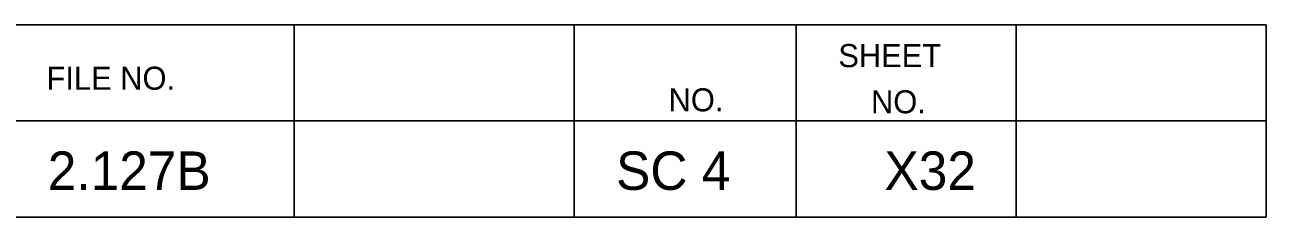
# Model space of a CAD drawing. Extents: x 1000 to 1162, y 999 to 8520.
# Drawn here: x 1145.41 to 1161.56, y 4665.05 to 4667.55 of the extents above; entities that cross this region are included whole.
import ezdxf

# ---------------------------------------------------------------- set-up
doc = ezdxf.new("R2010")
doc.units = 0
doc.layers.add('Level 20', color=7, linetype='Continuous')
doc.layers.add('Level 3', color=7, linetype='Continuous')

msp = doc.modelspace()

# ---------------------------------------------------------------- linework, layer by layer
at = {"layer": 'Level 3'}
for p, q in [((1133.055, 4667.546), (1161.555, 4667.546)), ((1133.055, 4667.546), (1161.555, 4667.546)), ((1133.055, 4667.546), (1161.555, 4667.546)), ((1133.055, 4667.546), (1161.555, 4667.546)), ((1133.055, 4667.546), (1161.555, 4667.546)), ((1133.055, 4667.546), (1161.555, 4667.546)), ((1133.055, 4667.546), (1161.555, 4667.546)), ((1133.055, 4667.546), (1161.555, 4667.546)), ((1133.055, 4667.546), (1161.555, 4667.546)), ((1133.055, 4667.546), (1161.555, 4667.546)), ((1133.055, 4667.546), (1161.555, 4667.546)), ((1133.055, 4667.546), (1161.555, 4667.546)), ((1133.055, 4667.546), (1161.555, 4667.546)), ((1133.055, 4667.546), (1161.555, 4667.546)), ((1133.055, 4667.546), (1161.555, 4667.546)), ((1133.055, 4667.546), (1161.555, 4667.546)), ((1133.055, 4667.546), (1161.555, 4667.546)), ((1133.055, 4667.546), (1161.555, 4667.546)), ((1133.055, 4667.546), (1161.555, 4667.546)), ((1133.055, 4667.546), (1161.555, 4667.546)), ((1133.055, 4667.546), (1161.555, 4667.546)), ((1133.055, 4667.546), (1161.555, 4667.546)), ((1133.055, 4667.546), (1161.555, 4667.546)), ((1133.055, 4667.546), (1161.555, 4667.546)), ((1133.055, 4667.546), (1161.555, 4667.546)), ((1133.055, 4667.546), (1161.555, 4667.546)), ((1133.055, 4667.546), (1161.555, 4667.546)), ((1133.055, 4667.546), (1161.555, 4667.546)), ((1133.055, 4667.546), (1161.555, 4667.546)), ((1133.055, 4667.546), (1161.555, 4667.546)), ((1148.913, 4667.546), (1148.913, 4665.046)), ((1148.913, 4667.546), (1148.913, 4665.046)), ((1148.913, 4667.546), (1148.913, 4665.046)), ((1148.913, 4667.546), (1148.913, 4665.046)), ((1148.913, 4667.546), (1148.913, 4665.046)), ((1148.913, 4667.546), (1148.913, 4665.046)), ((1148.913, 4667.546), (1148.913, 4665.046)), ((1148.913, 4667.546), (1148.913, 4665.046)), ((1148.913, 4667.546), (1148.913, 4665.046)), ((1148.913, 4667.546), (1148.913, 4665.046)), ((1148.913, 4667.546), (1148.913, 4665.046)), ((1148.913, 4667.546), (1148.913, 4665.046)), ((1148.913, 4667.546), (1148.913, 4665.046)), ((1148.913, 4667.546), (1148.913, 4665.046)), ((1148.913, 4667.546), (1148.913, 4665.046)), ((1148.913, 4667.546), (1148.913, 4665.046)), ((1148.913, 4667.546), (1148.913, 4665.046)), ((1148.913, 4667.546), (1148.913, 4665.046)), ((1148.913, 4667.546), (1148.913, 4665.046)), ((1148.913, 4667.546), (1148.913, 4665.046)), ((1148.913, 4667.546), (1148.913, 4665.046)), ((1148.913, 4667.546), (1148.913, 4665.046)), ((1148.913, 4667.546), (1148.913, 4665.046)), ((1148.913, 4667.546), (1148.913, 4665.046)), ((1148.913, 4667.546), (1148.913, 4665.046)), ((1148.913, 4667.546), (1148.913, 4665.046)), ((1148.913, 4667.546), (1148.913, 4665.046)), ((1148.913, 4667.546), (1148.913, 4665.046)), ((1148.913, 4667.546), (1148.913, 4665.046)), ((1148.913, 4667.546), (1148.913, 4665.046)), ((1152.554, 4667.546), (1152.554, 4665.046)), ((1152.554, 4667.546), (1152.554, 4665.046)), ((1152.554, 4667.546), (1152.554, 4665.046)), ((1152.554, 4667.546), (1152.554, 4665.046)), ((1152.554, 4667.546), (1152.554, 4665.046)), ((1152.554, 4667.546), (1152.554, 4665.046)), ((1152.554, 4667.546), (1152.554, 4665.046)), ((1152.554, 4667.546), (1152.554, 4665.046)), ((1152.554, 4667.546), (1152.554, 4665.046)), ((1152.554, 4667.546), (1152.554, 4665.046)), ((1152.554, 4667.546), (1152.554, 4665.046)), ((1152.554, 4667.546), (1152.554, 4665.046)), ((1152.554, 4667.546), (1152.554, 4665.046)), ((1152.554, 4667.546), (1152.554, 4665.046)), ((1152.554, 4667.546), (1152.554, 4665.046)), ((1152.554, 4667.546), (1152.554, 4665.046)), ((1152.554, 4667.546), (1152.554, 4665.046)), ((1152.554, 4667.546), (1152.554, 4665.046)), ((1152.554, 4667.546), (1152.554, 4665.046)), ((1152.554, 4667.546), (1152.554, 4665.046)), ((1152.554, 4667.546), (1152.554, 4665.046)), ((1152.554, 4667.546), (1152.554, 4665.046)), ((1152.554, 4667.546), (1152.554, 4665.046)), ((1152.554, 4667.546), (1152.554, 4665.046)), ((1152.554, 4667.546), (1152.554, 4665.046)), ((1152.554, 4667.546), (1152.554, 4665.046)), ((1152.554, 4667.546), (1152.554, 4665.046)), ((1152.554, 4667.546), (1152.554, 4665.046)), ((1152.554, 4667.546), (1152.554, 4665.046)), ((1152.554, 4667.546), (1152.554, 4665.046)), ((1155.44, 4667.546), (1155.44, 4665.046)), ((1155.44, 4667.546), (1155.44, 4665.046)), ((1155.44, 4667.546), (1155.44, 4665.046)), ((1155.44, 4667.546), (1155.44, 4665.046)), ((1155.44, 4667.546), (1155.44, 4665.046)), ((1155.44, 4667.546), (1155.44, 4665.046)), ((1155.44, 4667.546), (1155.44, 4665.046)), ((1155.44, 4667.546), (1155.44, 4665.046)), ((1155.44, 4667.546), (1155.44, 4665.046)), ((1155.44, 4667.546), (1155.44, 4665.046)), ((1155.44, 4667.546), (1155.44, 4665.046)), ((1155.44, 4667.546), (1155.44, 4665.046)), ((1155.44, 4667.546), (1155.44, 4665.046)), ((1155.44, 4667.546), (1155.44, 4665.046)), ((1155.44, 4667.546), (1155.44, 4665.046)), ((1155.44, 4667.546), (1155.44, 4665.046)), ((1155.44, 4667.546), (1155.44, 4665.046)), ((1155.44, 4667.546), (1155.44, 4665.046)), ((1155.44, 4667.546), (1155.44, 4665.046)), ((1155.44, 4667.546), (1155.44, 4665.046)), ((1155.44, 4667.546), (1155.44, 4665.046)), ((1155.44, 4667.546), (1155.44, 4665.046)), ((1155.44, 4667.546), (1155.44, 4665.046)), ((1155.44, 4667.546), (1155.44, 4665.046)), ((1155.44, 4667.546), (1155.44, 4665.046)), ((1155.44, 4667.546), (1155.44, 4665.046)), ((1155.44, 4667.546), (1155.44, 4665.046)), ((1155.44, 4667.546), (1155.44, 4665.046)), ((1155.44, 4667.546), (1155.44, 4665.046)), ((1155.44, 4667.546), (1155.44, 4665.046)), ((1158.305, 4667.546), (1158.305, 4665.046)), ((1158.305, 4667.546), (1158.305, 4665.046)), ((1158.305, 4667.546), (1158.305, 4665.046)), ((1158.305, 4667.546), (1158.305, 4665.046)), ((1158.305, 4667.546), (1158.305, 4665.046)), ((1158.305, 4667.546), (1158.305, 4665.046)), ((1158.305, 4667.546), (1158.305, 4665.046)), ((1158.305, 4667.546), (1158.305, 4665.046)), ((1158.305, 4667.546), (1158.305, 4665.046)), ((1158.305, 4667.546), (1158.305, 4665.046)), ((1158.305, 4667.546), (1158.305, 4665.046)), ((1158.305, 4667.546), (1158.305, 4665.046)), ((1158.305, 4667.546), (1158.305, 4665.046)), ((1158.305, 4667.546), (1158.305, 4665.046)), ((1158.305, 4667.546), (1158.305, 4665.046)), ((1158.305, 4667.546), (1158.305, 4665.046)), ((1158.305, 4667.546), (1158.305, 4665.046)), ((1158.305, 4667.546), (1158.305, 4665.046)), ((1158.305, 4667.546), (1158.305, 4665.046)), ((1158.305, 4667.546), (1158.305, 4665.046)), ((1158.305, 4667.546), (1158.305, 4665.046)), ((1158.305, 4667.546), (1158.305, 4665.046)), ((1158.305, 4667.546), (1158.305, 4665.046)), ((1158.305, 4667.546), (1158.305, 4665.046)), ((1158.305, 4667.546), (1158.305, 4665.046)), ((1158.305, 4667.546), (1158.305, 4665.046)), ((1158.305, 4667.546), (1158.305, 4665.046)), ((1158.305, 4667.546), (1158.305, 4665.046)), ((1158.305, 4667.546), (1158.305, 4665.046)), ((1158.305, 4667.546), (1158.305, 4665.046)), ((1161.555, 4667.546), (1161.555, 4665.046)), ((1161.555, 4667.546), (1161.555, 4665.046)), ((1161.555, 4667.546), (1161.555, 4665.046)), ((1161.555, 4667.546), (1161.555, 4665.046)), ((1161.555, 4667.546), (1161.555, 4665.046)), ((1161.555, 4667.546), (1161.555, 4665.046)), ((1161.555, 4667.546), (1161.555, 4665.046)), ((1161.555, 4667.546), (1161.555, 4665.046)), ((1161.555, 4667.546), (1161.555, 4665.046)), ((1161.555, 4667.546), (1161.555, 4665.046)), ((1161.555, 4667.546), (1161.555, 4665.046)), ((1161.555, 4667.546), (1161.555, 4665.046)), ((1161.555, 4667.546), (1161.555, 4665.046)), ((1161.555, 4667.546), (1161.555, 4665.046)), ((1161.555, 4667.546), (1161.555, 4665.046)), ((1161.555, 4667.546), (1161.555, 4665.046)), ((1161.555, 4667.546), (1161.555, 4665.046)), ((1161.555, 4667.546), (1161.555, 4665.046)), ((1161.555, 4667.546), (1161.555, 4665.046)), ((1161.555, 4667.546), (1161.555, 4665.046)), ((1161.555, 4667.546), (1161.555, 4665.046)), ((1161.555, 4667.546), (1161.555, 4665.046)), ((1161.555, 4667.546), (1161.555, 4665.046)), ((1161.555, 4667.546), (1161.555, 4665.046)), ((1161.555, 4667.546), (1161.555, 4665.046)), ((1161.555, 4667.546), (1161.555, 4665.046)), ((1161.555, 4667.546), (1161.555, 4665.046)), ((1161.555, 4667.546), (1161.555, 4665.046)), ((1161.555, 4667.546), (1161.555, 4665.046)), ((1161.555, 4667.546), (1161.555, 4665.046)), ((1133.055, 4666.296), (1161.555, 4666.296)), ((1133.055, 4666.296), (1161.555, 4666.296)), ((1133.055, 4666.296), (1161.555, 4666.296)), ((1133.055, 4666.296), (1161.555, 4666.296)), ((1133.055, 4666.296), (1161.555, 4666.296)), ((1133.055, 4666.296), (1161.555, 4666.296)), ((1133.055, 4666.296), (1161.555, 4666.296)), ((1133.055, 4666.296), (1161.555, 4666.296)), ((1133.055, 4666.296), (1161.555, 4666.296)), ((1133.055, 4666.296), (1161.555, 4666.296)), ((1133.055, 4666.296), (1161.555, 4666.296)), ((1133.055, 4666.296), (1161.555, 4666.296)), ((1133.055, 4666.296), (1161.555, 4666.296)), ((1133.055, 4666.296), (1161.555, 4666.296)), ((1133.055, 4666.296), (1161.555, 4666.296)), ((1133.055, 4666.296), (1161.555, 4666.296)), ((1133.055, 4666.296), (1161.555, 4666.296)), ((1133.055, 4666.296), (1161.555, 4666.296)), ((1133.055, 4666.296), (1161.555, 4666.296)), ((1133.055, 4666.296), (1161.555, 4666.296)), ((1133.055, 4666.296), (1161.555, 4666.296)), ((1133.055, 4666.296), (1161.555, 4666.296)), ((1133.055, 4666.296), (1161.555, 4666.296)), ((1133.055, 4666.296), (1161.555, 4666.296)), ((1133.055, 4666.296), (1161.555, 4666.296)), ((1133.055, 4666.296), (1161.555, 4666.296)), ((1133.055, 4666.296), (1161.555, 4666.296)), ((1133.055, 4666.296), (1161.555, 4666.296)), ((1133.055, 4666.296), (1161.555, 4666.296)), ((1133.055, 4666.296), (1161.555, 4666.296)), ((1133.055, 4665.046), (1161.555, 4665.046)), ((1133.055, 4665.046), (1161.555, 4665.046)), ((1133.055, 4665.046), (1161.555, 4665.046)), ((1133.055, 4665.046), (1161.555, 4665.046)), ((1133.055, 4665.046), (1161.555, 4665.046)), ((1133.055, 4665.046), (1161.555, 4665.046)), ((1133.055, 4665.046), (1161.555, 4665.046)), ((1133.055, 4665.046), (1161.555, 4665.046)), ((1133.055, 4665.046), (1161.555, 4665.046)), ((1133.055, 4665.046), (1161.555, 4665.046)), ((1133.055, 4665.046), (1161.555, 4665.046)), ((1133.055, 4665.046), (1161.555, 4665.046)), ((1133.055, 4665.046), (1161.555, 4665.046)), ((1133.055, 4665.046), (1161.555, 4665.046)), ((1133.055, 4665.046), (1161.555, 4665.046)), ((1133.055, 4665.046), (1161.555, 4665.046)), ((1133.055, 4665.046), (1161.555, 4665.046)), ((1133.055, 4665.046), (1161.555, 4665.046)), ((1133.055, 4665.046), (1161.555, 4665.046)), ((1133.055, 4665.046), (1161.555, 4665.046)), ((1133.055, 4665.046), (1161.555, 4665.046)), ((1133.055, 4665.046), (1161.555, 4665.046)), ((1133.055, 4665.046), (1161.555, 4665.046)), ((1133.055, 4665.046), (1161.555, 4665.046)), ((1133.055, 4665.046), (1161.555, 4665.046)), ((1133.055, 4665.046), (1161.555, 4665.046)), ((1133.055, 4665.046), (1161.555, 4665.046)), ((1133.055, 4665.046), (1161.555, 4665.046)), ((1133.055, 4665.046), (1161.555, 4665.046)), ((1133.055, 4665.046), (1161.555, 4665.046))]:
    msp.add_line(p, q, dxfattribs=at)

# ---------------------------------------------------------------- texts
at = {"layer": 'Level 20'}
for s, p in [('2.127B', (1145.707, 4665.4)), ('SC 4', (1153.099, 4665.4)), ('X32', (1156.59, 4665.4))]:
    msp.add_text(s, height=0.5, dxfattribs=at).set_placement(p)
at = {"layer": 'Level 3'}
for s, p in [('SHEET', (1155.99, 4666.996)), ('SHEET', (1155.99, 4666.996)), ('SHEET', (1155.99, 4666.996)), ('SHEET', (1155.99, 4666.996)), ('SHEET', (1155.99, 4666.996)), ('SHEET', (1155.99, 4666.996)), ('SHEET', (1155.99, 4666.996)), ('SHEET', (1155.99, 4666.996)), ('SHEET', (1155.99, 4666.996)), ('SHEET', (1155.99, 4666.996)), ('SHEET', (1155.99, 4666.996)), ('SHEET', (1155.99, 4666.996)), ('SHEET', (1155.99, 4666.996)), ('SHEET', (1155.99, 4666.996)), ('SHEET', (1155.99, 4666.996)), ('SHEET', (1155.99, 4666.996)), ('SHEET', (1155.99, 4666.996)), ('SHEET', (1155.99, 4666.996)), ('SHEET', (1155.99, 4666.996)), ('SHEET', (1155.99, 4666.996)), ('SHEET', (1155.99, 4666.996)), ('SHEET', (1155.99, 4666.996)), ('SHEET', (1155.99, 4666.996)), ('SHEET', (1155.99, 4666.996)), ('SHEET', (1155.99, 4666.996)), ('SHEET', (1155.99, 4666.996)), ('SHEET', (1155.99, 4666.996)), ('SHEET', (1155.99, 4666.996)), ('SHEET', (1155.99, 4666.996)), ('SHEET', (1155.99, 4666.996)), ('FILE NO.', (1145.691, 4666.702)), ('FILE NO.', (1145.691, 4666.702)), ('FILE NO.', (1145.691, 4666.702)), ('FILE NO.', (1145.691, 4666.702)), ('FILE NO.', (1145.691, 4666.702)), ('FILE NO.', (1145.691, 4666.702)), ('FILE NO.', (1145.691, 4666.702)), ('FILE NO.', (1145.691, 4666.702)), ('FILE NO.', (1145.691, 4666.702)), ('FILE NO.', (1145.691, 4666.702)), ('FILE NO.', (1145.691, 4666.702)), ('FILE NO.', (1145.691, 4666.702)), ('FILE NO.', (1145.691, 4666.702)), ('FILE NO.', (1145.691, 4666.702)), ('FILE NO.', (1145.691, 4666.702)), ('FILE NO.', (1145.691, 4666.702)), ('FILE NO.', (1145.691, 4666.702)), ('FILE NO.', (1145.691, 4666.702)), ('FILE NO.', (1145.691, 4666.702)), ('FILE NO.', (1145.691, 4666.702)), ('FILE NO.', (1145.691, 4666.702)), ('FILE NO.', (1145.691, 4666.702)), ('FILE NO.', (1145.691, 4666.702)), ('FILE NO.', (1145.691, 4666.702)), ('FILE NO.', (1145.691, 4666.702)), ('FILE NO.', (1145.691, 4666.702)), ('FILE NO.', (1145.691, 4666.702)), ('FILE NO.', (1145.691, 4666.702)), ('FILE NO.', (1145.691, 4666.702)), ('FILE NO.', (1145.691, 4666.702)), ('NO.', (1153.782, 4666.421)), ('NO.', (1153.782, 4666.421)), ('NO.', (1153.782, 4666.421)), ('NO.', (1153.782, 4666.421)), ('NO.', (1153.782, 4666.421)), ('NO.', (1153.782, 4666.421)), ('NO.', (1153.782, 4666.421)), ('NO.', (1153.782, 4666.421)), ('NO.', (1153.782, 4666.421)), ('NO.', (1153.782, 4666.421)), ('NO.', (1153.782, 4666.421)), ('NO.', (1153.782, 4666.421)), ('NO.', (1153.782, 4666.421)), ('NO.', (1153.782, 4666.421)), ('NO.', (1153.782, 4666.421)), ('NO.', (1153.782, 4666.421)), ('NO.', (1153.782, 4666.421)), ('NO.', (1153.782, 4666.421)), ('NO.', (1153.782, 4666.421)), ('NO.', (1153.782, 4666.421)), ('NO.', (1153.782, 4666.421)), ('NO.', (1153.782, 4666.421)), ('NO.', (1153.782, 4666.421)), ('NO.', (1153.782, 4666.421)), ('NO.', (1153.782, 4666.421)), ('NO.', (1153.782, 4666.421)), ('NO.', (1153.782, 4666.421)), ('NO.', (1153.782, 4666.421)), ('NO.', (1153.782, 4666.421)), ('NO.', (1153.782, 4666.421)), ('NO.', (1156.415, 4666.396)), ('NO.', (1156.415, 4666.396)), ('NO.', (1156.415, 4666.396)), ('NO.', (1156.415, 4666.396)), ('NO.', (1156.415, 4666.396)), ('NO.', (1156.415, 4666.396)), ('NO.', (1156.415, 4666.396)), ('NO.', (1156.415, 4666.396)), ('NO.', (1156.415, 4666.396)), ('NO.', (1156.415, 4666.396)), ('NO.', (1156.415, 4666.396)), ('NO.', (1156.415, 4666.396)), ('NO.', (1156.415, 4666.396)), ('NO.', (1156.415, 4666.396)), ('NO.', (1156.415, 4666.396)), ('NO.', (1156.415, 4666.396)), ('NO.', (1156.415, 4666.396)), ('NO.', (1156.415, 4666.396)), ('NO.', (1156.415, 4666.396)), ('NO.', (1156.415, 4666.396)), ('NO.', (1156.415, 4666.396)), ('NO.', (1156.415, 4666.396)), ('NO.', (1156.415, 4666.396)), ('NO.', (1156.415, 4666.396)), ('NO.', (1156.415, 4666.396)), ('NO.', (1156.415, 4666.396)), ('NO.', (1156.415, 4666.396)), ('NO.', (1156.415, 4666.396)), ('NO.', (1156.415, 4666.396)), ('NO.', (1156.415, 4666.396))]:
    msp.add_text(s, height=0.3, dxfattribs=at).set_placement(p)

doc.saveas('drawing.dxf')
